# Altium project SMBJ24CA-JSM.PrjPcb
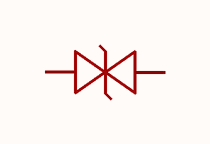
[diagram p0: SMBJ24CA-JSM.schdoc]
1 sheet, 1 parts. Net scope: global (net labels, ports and power ports of the same name join across sheets).

## Sheet SMBJ24CA-JSM.schdoc
size 127 x 101 mm

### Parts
D?  smbj24ca-jsm  [SMB_L4.5-W3.7-LS5.4-BI]  (value not drawn)

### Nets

Not connected (* = marked no-connect by the designer): D? 1(C) 2(A)

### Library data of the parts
D? = smbj24ca-jsm: 极性:双向;反向截止电压(Vrwm):24V;钳位电压:38.9V;峰值脉冲电流(Ipp):15.5A;峰值脉冲功率(Ppp):600W;击穿电压(VBR):29.5V;; Manufacturer: JSMSEMI(杰盛微); AddInBom: yes; ModelId: 65911100bcdc4390a7f360e322a6ac2c; ModelTransform: 212.598,144.488,0,0,0,0,0,0,0; Polarity: 双向; Reverse Stand-Off Voltage (Vrwm): 24V; Clamping Voltage: 38.9V; Peak Pulse Current (Ipp): 15.5A; Peak Pulse Power Dissipation (Ppp): 600W; Voltage - Breakdown: 29.5V; Reverse Leakage Current (Ir): 1uA; Number of Channels: 单路; Type: TVS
